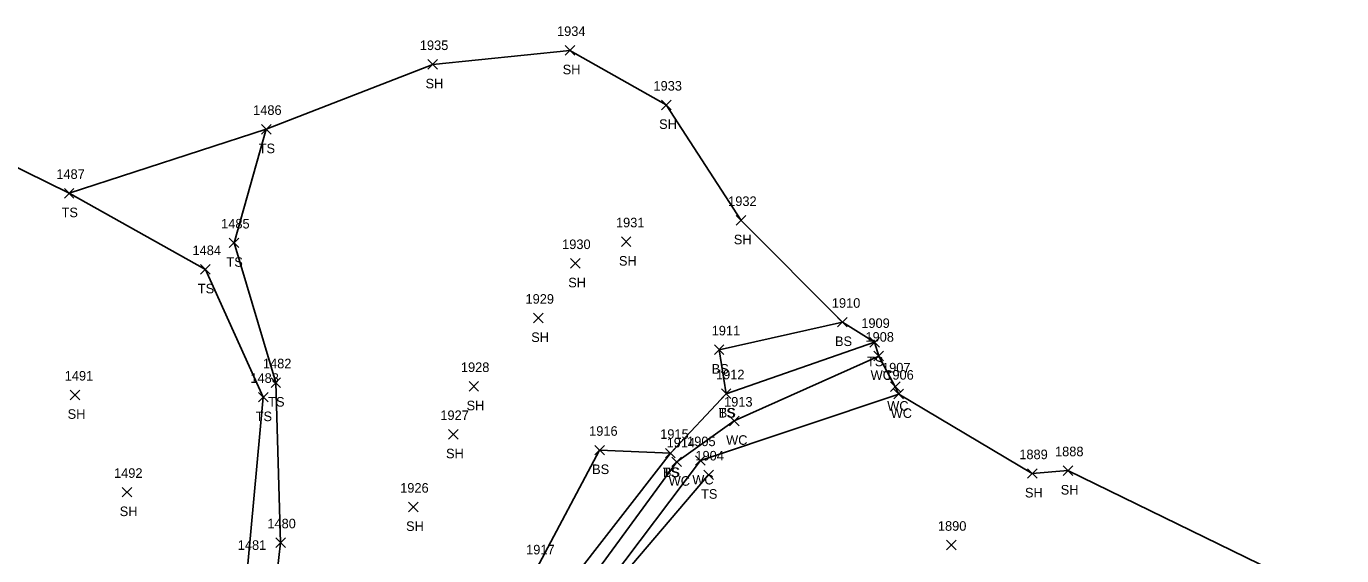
# Model space of a CAD drawing. Extents: x 1754529 to 1755810, y 621660 to 624656.
# Drawn here: x 1755027.6 to 1755302.4, y 624334.6 to 624445.2 of the extents above; entities that cross this region are included whole.
import ezdxf

# ---------------------------------------------------------------- set-up
doc = ezdxf.new("R2010")
doc.units = 0
for name, color, linetype in [('L_A', 7, 'Continuous'), ('L_I', 7, 'Continuous'), ('L_TIC', 7, 'Continuous'), ('LAWE', 7, 'Continuous'), ('LELB', 7, 'Continuous'), ('LSOGP', 7, 'Continuous')]:
    doc.layers.add(name, color=color, linetype=linetype)

msp = doc.modelspace()

# ---------------------------------------------------------------- linework, layer by layer
at = {"layer": 'L_TIC'}
for points in [[(1755140.17, 624439.17), (1755142.17, 624441.17)], [(1755142.17, 624439.17), (1755140.17, 624441.17)], [(1755111.52, 624436.23), (1755113.52, 624438.23)], [(1755113.52, 624436.23), (1755111.52, 624438.23)], [(1755160.31, 624427.75), (1755162.31, 624429.75)], [(1755162.31, 624427.75), (1755160.31, 624429.75)], [(1755076.76, 624422.68), (1755078.76, 624424.68)], [(1755078.76, 624422.68), (1755076.76, 624424.68)], [(1755035.59, 624409.3), (1755037.59, 624411.3)], [(1755037.59, 624409.3), (1755035.59, 624411.3)], [(1755175.92, 624403.64), (1755177.92, 624405.64)], [(1755177.92, 624403.64), (1755175.92, 624405.64)], [(1755070.03, 624398.94), (1755072.03, 624400.94)], [(1755072.03, 624398.94), (1755070.03, 624400.94)], [(1755151.92, 624399.18), (1755153.92, 624401.18)], [(1755153.92, 624399.18), (1755151.92, 624401.18)], [(1755064.05, 624393.38), (1755066.05, 624395.38)], [(1755066.05, 624393.38), (1755064.05, 624395.38)], [(1755141.33, 624394.64), (1755143.33, 624396.64)], [(1755143.33, 624394.64), (1755141.33, 624396.64)], [(1755133.6, 624383.22), (1755135.6, 624385.22)], [(1755135.6, 624383.22), (1755133.6, 624385.22)], [(1755197.09, 624382.37), (1755199.09, 624384.37)], [(1755199.09, 624382.37), (1755197.09, 624384.37)], [(1755171.34, 624376.6), (1755173.34, 624378.6)], [(1755173.34, 624376.6), (1755171.34, 624378.6)], [(1755203.81, 624378.16), (1755205.81, 624380.16)], [(1755205.81, 624378.16), (1755203.81, 624380.16)], [(1755204.67, 624375.28), (1755206.67, 624377.28)], [(1755206.67, 624375.28), (1755204.67, 624377.28)], [(1755078.75, 624369.72), (1755080.75, 624371.72)], [(1755080.75, 624369.72), (1755078.75, 624371.72)], [(1755120.11, 624368.95), (1755122.11, 624370.95)], [(1755122.11, 624368.95), (1755120.11, 624370.95)], [(1755208.13, 624368.86), (1755210.13, 624370.86)], [(1755210.13, 624368.86), (1755208.13, 624370.86)], [(1755036.79, 624367.16), (1755038.79, 624369.16)], [(1755038.79, 624367.16), (1755036.79, 624369.16)], [(1755076.13, 624366.68), (1755078.13, 624368.68)], [(1755078.13, 624366.68), (1755076.13, 624368.68)], [(1755172.81, 624367.42), (1755174.81, 624369.42)], [(1755174.81, 624367.42), (1755172.81, 624369.42)], [(1755172.81, 624367.42), (1755174.81, 624369.42)], [(1755174.81, 624367.42), (1755172.81, 624369.42)], [(1755208.86, 624367.35), (1755210.86, 624369.35)], [(1755210.86, 624367.35), (1755208.86, 624369.35)], [(1755174.49, 624361.73), (1755176.49, 624363.73)], [(1755176.49, 624361.73), (1755174.49, 624363.73)], [(1755115.81, 624358.91), (1755117.81, 624360.91)], [(1755117.81, 624358.91), (1755115.81, 624360.91)], [(1755146.37, 624355.62), (1755148.37, 624357.62)], [(1755148.37, 624355.62), (1755146.37, 624357.62)], [(1755161.16, 624354.98), (1755163.16, 624356.98)], [(1755163.16, 624354.98), (1755161.16, 624356.98)], [(1755161.16, 624354.98), (1755163.16, 624356.98)], [(1755163.16, 624354.98), (1755161.16, 624356.98)], [(1755162.49, 624353.18), (1755164.49, 624355.18)], [(1755164.49, 624353.18), (1755162.49, 624355.18)], [(1755167.42, 624353.45), (1755169.42, 624355.45)], [(1755169.42, 624353.45), (1755167.42, 624355.45)], [(1755169.15, 624350.46), (1755171.15, 624352.46)], [(1755171.15, 624350.46), (1755169.15, 624352.46)], [(1755236.73, 624350.73), (1755238.73, 624352.73)], [(1755238.73, 624350.73), (1755236.73, 624352.73)], [(1755244.19, 624351.34), (1755246.19, 624353.34)], [(1755246.19, 624351.34), (1755244.19, 624353.34)], [(1755047.66, 624346.83), (1755049.66, 624348.83)], [(1755049.66, 624346.83), (1755047.66, 624348.83)], [(1755107.47, 624343.73), (1755109.47, 624345.73)], [(1755109.47, 624343.73), (1755107.47, 624345.73)], [(1755079.76, 624336.28), (1755081.76, 624338.28)], [(1755081.76, 624336.28), (1755079.76, 624338.28)], [(1755219.81, 624335.77), (1755221.81, 624337.77)], [(1755221.81, 624335.77), (1755219.81, 624337.77)]]:
    msp.add_lwpolyline(points, dxfattribs=at)
at = {"layer": 'LAWE'}
for points in [[(1755205.67, 624376.28), (1755175.49, 624362.73), (1755163.49, 624354.18), (1755142.21, 624325.07), (1755136.43, 624314.36), (1755137.75, 624306.01)], [(1755173.74, 623956.25), (1755179.49, 623981.26), (1755189.19, 624018.36), (1755179.71, 624027.81), (1755177.17, 624037.31), (1755183.05, 624071.07), (1755186.59, 624109.3), (1755195.76, 624123.49), (1755204.15, 624140.63), (1755199.7, 624157.52), (1755189.07, 624181.84), (1755178.94, 624196.44), (1755167.9, 624207.95), (1755156.07, 624245.11), (1755149.51, 624271.99), (1755152.32, 624294.92), (1755143.66, 624313.83), (1755149.45, 624329.22), (1755168.42, 624354.45), (1755209.86, 624368.35), (1755209.13, 624369.86)]]:
    msp.add_lwpolyline(points, dxfattribs=at)
at = {"layer": 'LELB'}
for points in [[(1755139.04, 624115.61), (1755146.37, 624123.46), (1755138.82, 624137.58), (1755123.57, 624162.31), (1755113.43, 624179.53), (1755086.23, 624212.44), (1755082.86, 624229.74), (1755080.02, 624248.74), (1755085.06, 624291.34), (1755077.56, 624309.64), (1755080.76, 624337.28), (1755079.75, 624370.72), (1755071.03, 624399.94), (1755077.76, 624423.68)], [(1755139.04, 624115.61), (1755135.04, 624134.99), (1755120.88, 624159.14), (1755108.49, 624174.55), (1755081.03, 624201.93), (1755079.94, 624225.73), (1755076.51, 624247.96), (1755080.69, 624289.64), (1755074.01, 624309.47), (1755073.93, 624332.78), (1755077.13, 624367.68), (1755065.05, 624394.38), (1755036.59, 624410.3), (1755018.14, 624419.38)], [(1755198.09, 624383.37), (1755172.34, 624377.6), (1755173.81, 624368.42)], [(1755204.81, 624379.16), (1755173.81, 624368.42), (1755162.16, 624355.98), (1755139.84, 624327.23), (1755134.08, 624309.6)], [(1755162.16, 624355.98), (1755147.37, 624356.62), (1755134.16, 624331.83), (1755128.27, 624320.33), (1755134.08, 624309.6)], [(1755179.93, 623958.52), (1755184.68, 623980.7), (1755191.18, 624019.58), (1755181.19, 624028.74), (1755178.62, 624037.28), (1755185, 624070.71), (1755187.96, 624108.96), (1755197.92, 624122.33), (1755209.55, 624141.51), (1755204.36, 624157.97), (1755190.25, 624182.31), (1755180.73, 624197.48), (1755169.22, 624208.69), (1755158.15, 624245.97), (1755151.05, 624272.57), (1755153.5, 624295.6), (1755146.12, 624314.43), (1755150.89, 624328.89), (1755170.15, 624351.46)]]:
    msp.add_lwpolyline(points, dxfattribs=at)
at = {"layer": 'LSOGP'}
msp.add_lwpolyline([(1755302.36, 624324.44), (1755245.19, 624352.34), (1755237.73, 624351.73), (1755209.86, 624368.35), (1755209.13, 624369.86), (1755205.67, 624376.28), (1755204.81, 624379.16), (1755198.09, 624383.37), (1755176.92, 624404.64), (1755161.31, 624428.75), (1755141.17, 624440.17), (1755112.52, 624437.23), (1755077.76, 624423.68), (1755036.59, 624410.3), (1755018.14, 624419.38)], dxfattribs=at)

# ---------------------------------------------------------------- texts
at = {"layer": 'L_A'}
for s, p in [('SH', (1755139.66, 624435.17)), ('SH', (1755111.01, 624432.23)), ('SH', (1755159.8, 624423.75)), ('TS', (1755076.17, 624418.68)), ('TS', (1755035, 624405.3)), ('SH', (1755175.4, 624399.64)), ('TS', (1755069.44, 624394.94)), ('SH', (1755151.41, 624395.18)), ('SH', (1755140.82, 624390.64)), ('TS', (1755063.46, 624389.38)), ('SH', (1755133.09, 624379.22)), ('BS', (1755196.53, 624378.37)), ('TS', (1755203.22, 624374.16)), ('BS', (1755170.78, 624372.6)), ('WC', (1755203.98, 624371.28)), ('TS', (1755078.16, 624365.72)), ('SH', (1755036.27, 624363.16)), ('TS', (1755075.54, 624362.68)), ('SH', (1755119.59, 624364.95)), ('TS', (1755172.22, 624363.42)), ('BS', (1755172.25, 624363.42)), ('WC', (1755207.44, 624364.86)), ('WC', (1755208.17, 624363.35)), ('WC', (1755173.8, 624357.73)), ('SH', (1755115.3, 624354.91)), ('BS', (1755145.81, 624351.62)), ('TS', (1755160.57, 624350.98)), ('BS', (1755160.6, 624350.98)), ('WC', (1755161.8, 624349.18)), ('WC', (1755166.73, 624349.45)), ('TS', (1755168.56, 624346.46)), ('SH', (1755236.21, 624346.73)), ('SH', (1755243.68, 624347.34)), ('SH', (1755047.15, 624342.83)), ('SH', (1755106.95, 624339.73))]:
    msp.add_text(s, height=2, dxfattribs=at).set_placement(p)
at = {"layer": 'L_I'}
for s, p in [('1934', (1755138.48, 624443.17)), ('1935', (1755109.83, 624440.23)), ('1933', (1755158.62, 624431.75)), ('1486', (1755075.01, 624426.68)), ('1487', (1755033.9, 624413.3)), ('1932', (1755174.22, 624407.64)), ('1485', (1755068.33, 624402.94)), ('1931', (1755150.79, 624403.18)), ('1930', (1755139.55, 624398.64)), ('1484', (1755062.35, 624397.38)), ('1929', (1755131.9, 624387.22)), ('1910', (1755195.88, 624386.37)), ('1909', (1755202.03, 624382.16)), ('1911', (1755170.78, 624380.6)), ('1908', (1755202.9, 624379.28)), ('1482', (1755077.06, 624373.72)), ('1491', (1755035.66, 624371.16)), ('1928', (1755118.41, 624372.95)), ('1912', (1755171.68, 624371.42)), ('1912', (1755171.68, 624371.42)), ('1907', (1755206.36, 624372.86)), ('1906', (1755207.04, 624371.35)), ('1483', (1755074.44, 624370.68)), ('1913', (1755173.37, 624365.73)), ('1927', (1755114.11, 624362.91)), ('1916', (1755145.19, 624359.62)), ('1915', (1755160.03, 624358.98)), ('1915', (1755160.03, 624358.98)), ('1914', (1755161.37, 624357.18)), ('1905', (1755165.65, 624357.45)), ('1904', (1755167.38, 624354.46)), ('1889', (1755235.03, 624354.73)), ('1888', (1755242.49, 624355.34)), ('1492', (1755045.96, 624350.83)), ('1926', (1755105.72, 624347.73)), ('1480', (1755077.98, 624340.28)), ('1890', (1755218.03, 624339.77)), ('1481', (1755071.8, 624335.78)), ('1917', (1755132.03, 624334.83))]:
    msp.add_text(s, height=2, dxfattribs=at).set_placement(p)

doc.saveas('drawing.dxf')
